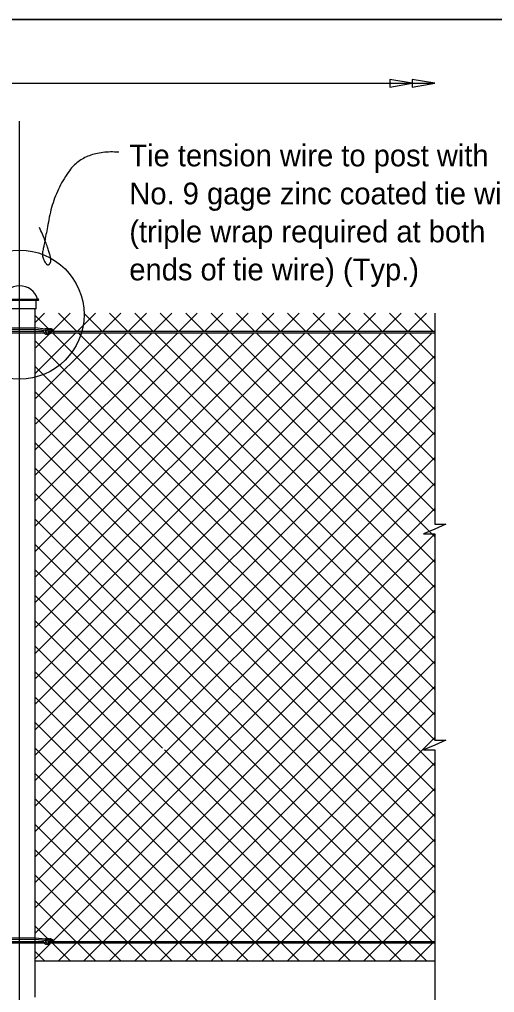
# Model space of a CAD drawing. Extents: x 0 to 41.1, y 0 to 25.9.
# Drawn here: x 24.62 to 29.01, y 16.93 to 25.95 of the extents above; entities that cross this region are included whole.
import ezdxf

# ---------------------------------------------------------------- set-up
doc = ezdxf.new("R2010")
doc.units = 0
for name, color, linetype in [('ActivePts-ConstElements', 7, 'Continuous'), ('CL_Major', 7, 'Continuous'), ('Dimension', 7, 'Continuous'), ('Miscellaneous', 7, 'Continuous'), ('Miscellaneous1', 7, 'Continuous'), ('SteelMisc', 7, 'Continuous'), ('SteelMisc_h', 7, 'Continuous'), ('SupstrConc', 7, 'Continuous')]:
    doc.layers.add(name, color=color, linetype=linetype)

msp = doc.modelspace()

# ---------------------------------------------------------------- linework, layer by layer
at = {"layer": 'ActivePts-ConstElements'}
msp.add_lwpolyline([(0, 0), (41.0506, 0), (41.0506, 25.9461), (0, 25.9461)], close=True, dxfattribs=at)
msp.add_lwpolyline([(0, 0), (41.0506, 0), (41.0506, 25.9461), (0, 25.9461)], close=True, dxfattribs=at)
msp.add_lwpolyline([(0, 0), (41.0506, 0), (41.0506, 25.9461), (0, 25.9461)], close=True, dxfattribs=at)
at = {"layer": 'CL_Major'}
msp.add_line((24.6151, 11.6734), (24.6151, 25.0052), dxfattribs=at)
at = {"layer": 'Dimension'}
for points in [[(13.615, 25.3556), (15.0787, 25.3556), (15.0787, 25.4589), (15.1237, 25.3556), (15.1687, 25.2523), (15.1687, 25.3556), (28.4596, 25.3556)], [(28.4596, 23.2265), (28.4596, 21.2702), (28.5629, 21.2702), (28.4596, 21.2252), (28.3562, 21.1802), (28.4596, 21.1802), (28.4596, 20.2867)], [(28.4596, 20.2867), (28.4596, 19.2689), (28.5629, 19.2689), (28.4596, 19.2239), (28.3562, 19.1789), (28.4596, 19.1789), (28.4596, 16.9746)], [(28.4596, 17.2246), (28.4596, 15.3737), (28.5629, 15.3737), (28.4596, 15.3287), (28.3562, 15.2837), (28.4596, 15.2837), (28.4596, 13.7412)]]:
    msp.add_lwpolyline(points, dxfattribs=at)
for points in [[(28.2513, 25.3556), (28.0431, 25.3909), (28.0431, 25.3203)], [(28.4596, 25.3556), (28.2513, 25.3909), (28.2513, 25.3203)]]:
    msp.add_lwpolyline(points, close=True, dxfattribs=at)
msp.add_circle((24.615, 23.212), 0.5976, dxfattribs=at)
msp.add_open_spline([(25.5348, 24.717), (25.216, 24.7369), (24.9346, 24.348), (24.8419, 23.852), (24.8201, 23.7498), (24.8799, 23.6501), (24.9246, 23.7397), (24.8002, 24.019)], degree=2, dxfattribs=at)
at = {"layer": 'Miscellaneous'}
for p, q in [((24.7609, 23.1379), (24.8475, 23.2245)), ((24.7609, 23.2036), (24.8832, 23.0814)), ((24.928, 23.0694), (25.0832, 23.2245)), ((24.9757, 23.2245), (25.1424, 23.0578)), ((25.1522, 23.0578), (25.3189, 23.2245)), ((25.2114, 23.2245), (25.3781, 23.0578)), ((25.3879, 23.0578), (25.5546, 23.2245)), ((25.4471, 23.2245), (25.6138, 23.0578)), ((25.6236, 23.0578), (25.7903, 23.2245)), ((25.6828, 23.2245), (25.8495, 23.0578)), ((25.8593, 23.0578), (26.026, 23.2245)), ((25.9185, 23.2245), (26.0852, 23.0578)), ((26.095, 23.0578), (26.2617, 23.2245)), ((26.1542, 23.2245), (26.3209, 23.0578)), ((26.3307, 23.0578), (26.4974, 23.2245)), ((26.3899, 23.2245), (26.5566, 23.0578)), ((26.5664, 23.0578), (26.7331, 23.2245)), ((26.6257, 23.2245), (26.7923, 23.0578)), ((26.8021, 23.0578), (26.9688, 23.2245)), ((26.8614, 23.2245), (27.028, 23.0578)), ((27.0378, 23.0578), (27.2045, 23.2245)), ((27.0971, 23.2245), (27.2637, 23.0578)), ((27.2735, 23.0578), (27.4402, 23.2245)), ((27.3328, 23.2245), (27.4994, 23.0578)), ((27.5092, 23.0578), (27.6759, 23.2245)), ((27.5685, 23.2245), (27.7351, 23.0578)), ((27.7449, 23.0578), (27.9116, 23.2245)), ((27.8042, 23.2245), (27.9708, 23.0578)), ((27.9806, 23.0578), (28.1473, 23.2245)), ((28.0399, 23.2245), (28.2065, 23.0578)), ((28.2163, 23.0578), (28.383, 23.2245)), ((28.2756, 23.2245), (28.4422, 23.0578)), ((24.7609, 20.0738), (27.7302, 23.0431)), ((24.7609, 20.5452), (27.2588, 23.0431)), ((24.7609, 21.0166), (26.7874, 23.0431)), ((24.7609, 21.488), (26.316, 23.0431)), ((24.7609, 19.6024), (28.2016, 23.0431)), ((24.7609, 21.7237), (26.0803, 23.0431)), ((24.7609, 21.2523), (26.5517, 23.0431)), ((24.7609, 20.7809), (27.0231, 23.0431)), ((24.7609, 20.3095), (27.4945, 23.0431)), ((24.7609, 19.8381), (27.9659, 23.0431)), ((24.7609, 19.3667), (28.4373, 23.0431)), ((24.7609, 21.9594), (25.8446, 23.0431)), ((24.7609, 22.4308), (25.3732, 23.0431)), ((24.7609, 22.6665), (25.1375, 23.0431)), ((24.7609, 22.9022), (24.8904, 23.0317)), ((24.7653, 22.1995), (25.6089, 23.0431)), ((24.9165, 23.0578), (24.921, 23.0623)), ((24.9214, 23.0431), (28.4595, 19.505)), ((25.1572, 23.0431), (28.4595, 19.7407)), ((25.3929, 23.0431), (28.4595, 19.9764)), ((25.6286, 23.0431), (28.4595, 20.2121)), ((25.8643, 23.0431), (28.4595, 20.4478)), ((26.1, 23.0431), (28.4595, 20.6835)), ((26.3357, 23.0431), (28.4595, 20.9192)), ((26.5714, 23.0431), (28.4595, 21.1549)), ((26.8071, 23.0431), (28.4595, 21.3906)), ((27.0428, 23.0431), (28.4595, 21.6263)), ((27.2785, 23.0431), (28.4595, 21.862)), ((27.5142, 23.0431), (28.4595, 22.0977)), ((27.7499, 23.0431), (28.4595, 22.3334)), ((27.9856, 23.0431), (28.4595, 22.5691)), ((28.2213, 23.0431), (28.4595, 22.8048)), ((24.7609, 22.9679), (28.4595, 19.2693)), ((24.7609, 19.131), (28.4595, 22.8296)), ((24.7609, 22.7322), (28.4595, 19.0336)), ((24.7609, 18.8953), (28.4595, 22.5939)), ((24.7609, 22.4965), (28.4595, 18.7979)), ((24.7609, 18.6596), (28.4595, 22.3582)), ((24.7609, 22.2608), (28.4595, 18.5622)), ((24.7609, 18.4239), (28.4595, 22.1225)), ((24.7609, 22.0251), (28.4595, 18.3265)), ((24.7609, 18.1882), (28.4595, 21.8868)), ((24.7609, 21.7894), (28.4595, 18.0908)), ((24.7609, 17.9525), (28.4595, 21.6511)), ((24.7609, 21.5537), (28.4595, 17.8551)), ((24.7609, 17.7168), (28.4595, 21.4154)), ((24.7609, 21.318), (28.4595, 17.6194)), ((24.7609, 17.4811), (28.4595, 21.1797)), ((24.7609, 21.0823), (28.4373, 17.4059)), ((24.9303, 17.4148), (28.4595, 20.944)), ((24.7609, 20.8466), (28.2016, 17.4059)), ((25.1572, 17.4059), (28.4595, 20.7083)), ((24.7609, 20.6109), (27.9659, 17.4059)), ((25.3929, 17.4059), (28.4595, 20.4726)), ((24.7609, 20.3752), (25.9395, 19.1966)), ((25.6286, 17.4059), (28.4595, 20.2369)), ((24.7609, 20.1395), (27.4945, 17.4059)), ((25.8643, 17.4059), (28.4595, 20.0012)), ((24.7609, 19.9038), (27.2588, 17.4059)), ((26.1, 17.4059), (28.4595, 19.7655)), ((24.7609, 19.6681), (27.0231, 17.4059)), ((26.3357, 17.4059), (28.4595, 19.5298)), ((24.7609, 19.4324), (26.7874, 17.4059)), ((26.5714, 17.4059), (28.4595, 19.2941)), ((24.7609, 19.1967), (26.5517, 17.4059)), ((25.9572, 19.1789), (27.7302, 17.4059)), ((26.8071, 17.4059), (28.4595, 19.0584)), ((24.7609, 18.961), (26.316, 17.4059)), ((27.0428, 17.4059), (28.4595, 18.8227)), ((24.7609, 18.7253), (26.0803, 17.4059)), ((27.2785, 17.4059), (28.4595, 18.587)), ((24.7609, 18.4896), (25.8446, 17.4059)), ((27.5142, 17.4059), (28.4595, 18.3513)), ((24.7609, 18.2539), (25.6089, 17.4059)), ((27.7499, 17.4059), (28.4595, 18.1156)), ((24.7609, 18.0182), (25.3732, 17.4059)), ((27.9856, 17.4059), (28.4595, 17.8799)), ((24.7609, 17.7825), (25.1375, 17.4059)), ((28.2213, 17.4059), (28.4595, 17.6442)), ((24.7609, 17.5468), (24.8783, 17.4294)), ((24.7609, 17.2454), (24.8992, 17.3837)), ((24.7641, 17.3078), (24.8475, 17.2245)), ((24.9165, 17.3912), (25.0832, 17.2245)), ((24.9757, 17.2245), (25.1424, 17.3912)), ((25.1522, 17.3912), (25.3189, 17.2245)), ((25.2114, 17.2245), (25.3781, 17.3912)), ((25.3879, 17.3912), (25.5546, 17.2245)), ((25.4471, 17.2245), (25.6138, 17.3912)), ((25.6236, 17.3912), (25.7903, 17.2245)), ((25.6828, 17.2245), (25.8495, 17.3912)), ((25.8593, 17.3912), (26.026, 17.2245)), ((25.9185, 17.2245), (26.0852, 17.3912)), ((26.095, 17.3912), (26.2617, 17.2245)), ((26.1542, 17.2245), (26.3209, 17.3912)), ((26.3307, 17.3912), (26.4974, 17.2245)), ((26.3899, 17.2245), (26.5566, 17.3912)), ((26.5664, 17.3912), (26.7331, 17.2245)), ((26.6257, 17.2245), (26.7923, 17.3912)), ((26.8021, 17.3912), (26.9688, 17.2245)), ((26.8614, 17.2245), (27.028, 17.3912)), ((27.0378, 17.3912), (27.2045, 17.2245)), ((27.0971, 17.2245), (27.2637, 17.3912)), ((27.2735, 17.3912), (27.4402, 17.2245)), ((27.3328, 17.2245), (27.4994, 17.3912)), ((27.5092, 17.3912), (27.6759, 17.2245)), ((27.5685, 17.2245), (27.7351, 17.3912)), ((27.7449, 17.3912), (27.9116, 17.2245)), ((27.8042, 17.2245), (27.9708, 17.3912)), ((27.9806, 17.3912), (28.1473, 17.2245)), ((28.0399, 17.2245), (28.2065, 17.3912)), ((28.2163, 17.3912), (28.383, 17.2245)), ((28.2756, 17.2245), (28.4422, 17.3912))]:
    msp.add_line(p, q, dxfattribs=at)
at = {"layer": 'Miscellaneous1'}
msp.add_lwpolyline([(0, 25.9461), (41.0506, 25.9461), (41.0506, 0), (0, 0)], close=True, dxfattribs=at)
at = {"layer": 'SteelMisc'}
for p, q in [((24.4427, 23.3564), (24.7873, 23.3564)), ((24.7873, 23.3442), (24.4427, 23.3442)), ((24.7691, 23.2645), (24.461, 23.2645)), ((24.7609, 16.8894), (24.7609, 23.2644)), ((24.7691, 23.2645), (24.7691, 23.3442)), ((24.4692, 23.0904), (24.7604, 23.0921)), ((24.4692, 23.0759), (24.7604, 23.0776)), ((24.7604, 23.0921), (24.8547, 23.081)), ((24.7604, 23.0776), (24.8525, 23.0682)), ((24.7609, 23.0578), (24.8413, 23.0578)), ((24.7609, 23.0431), (24.8439, 23.0431)), ((24.9067, 23.0431), (28.4595, 23.0431)), ((24.9116, 23.0578), (24.9269, 23.0578)), ((24.9353, 23.0578), (28.4595, 23.0578)), ((24.4692, 17.4385), (24.7604, 17.4402)), ((24.4692, 17.424), (24.7604, 17.4257)), ((24.7604, 17.4402), (24.8547, 17.4291)), ((24.7604, 17.4257), (24.8525, 17.4163)), ((24.7609, 17.4059), (24.8413, 17.4059)), ((24.9116, 17.4059), (24.9269, 17.4059)), ((24.9353, 17.4059), (28.4595, 17.4059)), ((24.7609, 17.3912), (24.8439, 17.3912)), ((24.9059, 17.3912), (28.4595, 17.3912))]:
    msp.add_line(p, q, dxfattribs=at)
msp.add_arc((24.7872, 23.3502), 0.00613, 271.1647, 88.8353, dxfattribs=at)
for centre, major_axis, ratio, start_param, end_param in [((24.6157, 23.3154), (0.1711, 0), 0.957868, 0.252602, 2.888574), ((24.8556, 23.0562), (0.0303, -0.0108), 0.724765, 6.241815, 8.212701), ((24.8691, 23.0544), (-0.0295, 0), 0.957868, 2.243629, 5.062245), ((24.8879, 23.0598), (-0.023, 0), 0.957868, 3.312645, 4.992926), ((24.9004, 23.0453), (-0.0373, 0), 0.957868, 3.175144, 4.79635), ((24.8661, 23.0543), (-0.0251, 0), 0.957868, 0.055352, 0.751829), ((24.8661, 23.0543), (-0.0251, 0), 0.957868, 5.673972, 5.875498), ((24.8732, 23.0664), (-0.0391, 0), 0.957868, 0.863445, 1.200597), ((24.8506, 23.0433), (0.0259, 0), 0.957868, 0.655696, 1.505671), ((24.8663, 23.0556), (-0.0119, 0), 0.957868, 5.149694, 6.840495), ((24.8663, 23.0556), (-0.0119, 0), 0.957868, 0.560069, 0.643501), ((24.8646, 23.0498), (0.00795, 0), 0.957868, 3.252108, 6.425997), ((24.8658, 23.0476), (-0.0206, -0.0021), 0.798607, 1.063032, 2.950031), ((24.859, 23.0521), (0.0139, 0), 0.957868, 5.660958, 7.342751), ((24.8792, 23.0476), (-0.0206, -0.0021), 0.798607, 1.063032, 1.956656), ((24.8853, 23.0533), (-0.0231, 0), 0.957868, 1.403365, 2.503632), ((24.8867, 23.0573), (0.0249, 0), 0.957868, 5.476514, 6.557353), ((24.8792, 23.0056), (0.0724, 0), 0.957868, 0.631079, 1.121037), ((24.8661, 17.4024), (-0.0251, 0), 0.957868, 0.055352, 0.751829), ((24.8661, 17.4024), (-0.0251, 0), 0.957868, 5.673972, 5.875498), ((24.8556, 17.4043), (0.0303, -0.0108), 0.724765, 6.241815, 8.212701), ((24.8506, 17.3914), (0.0259, 0), 0.957868, 0.655696, 1.505671), ((24.8663, 17.4036), (-0.0119, 0), 0.957868, 5.149694, 6.840495), ((24.8663, 17.4036), (-0.0119, 0), 0.957868, 0.560069, 0.643501), ((24.8646, 17.3979), (0.00795, 0), 0.957868, 3.252108, 6.425997), ((24.8691, 17.4025), (-0.0295, 0), 0.957868, 2.243629, 5.062245), ((24.859, 17.4002), (0.0139, 0), 0.957868, 5.660958, 7.342751), ((24.8879, 17.4079), (-0.023, 0), 0.957868, 3.312645, 4.992926), ((24.9004, 17.3934), (-0.0373, 0), 0.957868, 3.175144, 4.79635), ((24.8867, 17.4054), (0.0249, 0), 0.957868, 5.476514, 6.557353), ((24.8792, 17.3537), (0.0724, 0), 0.957868, 0.631079, 1.121037), ((24.8732, 17.4144), (-0.0391, 0), 0.957868, 0.863445, 1.200597), ((24.8658, 17.3957), (-0.0206, -0.0021), 0.798607, 1.063032, 2.950031), ((24.8792, 17.3957), (-0.0206, -0.0021), 0.798607, 1.063032, 1.956656), ((24.8853, 17.4014), (-0.0231, 0), 0.957868, 1.403365, 2.503632)]:
    msp.add_ellipse(centre, major_axis=major_axis, ratio=ratio, start_param=start_param, end_param=end_param, dxfattribs=at)
at = {"layer": 'SteelMisc_h'}
for p, q in [((24.4692, 23.0578), (24.7609, 23.0578)), ((24.4692, 23.0431), (24.7609, 23.0431)), ((24.4692, 17.4059), (24.7609, 17.4059)), ((24.4692, 17.3912), (24.7609, 17.3912))]:
    msp.add_line(p, q, dxfattribs=at)
at = {"layer": 'SupstrConc'}
for q in [(28.4595, 17.2245), (26.002, 17.2245)]:
    msp.add_line((24.7609, 17.2245), q, dxfattribs=at)

# ---------------------------------------------------------------- texts
at = {"layer": 'Dimension'}
for s, p in [('Tie tension wire to post with ', (25.632, 24.5853)), ('No. 9 gage zinc coated tie wire ', (25.632, 24.2333)), ('(triple wrap required at both ', (25.632, 23.8813)), ('ends of tie wire) (Typ.)', (25.632, 23.5293))]:
    msp.add_text(s, height=0.2016, dxfattribs=at).set_placement(p)

doc.saveas('drawing.dxf')
